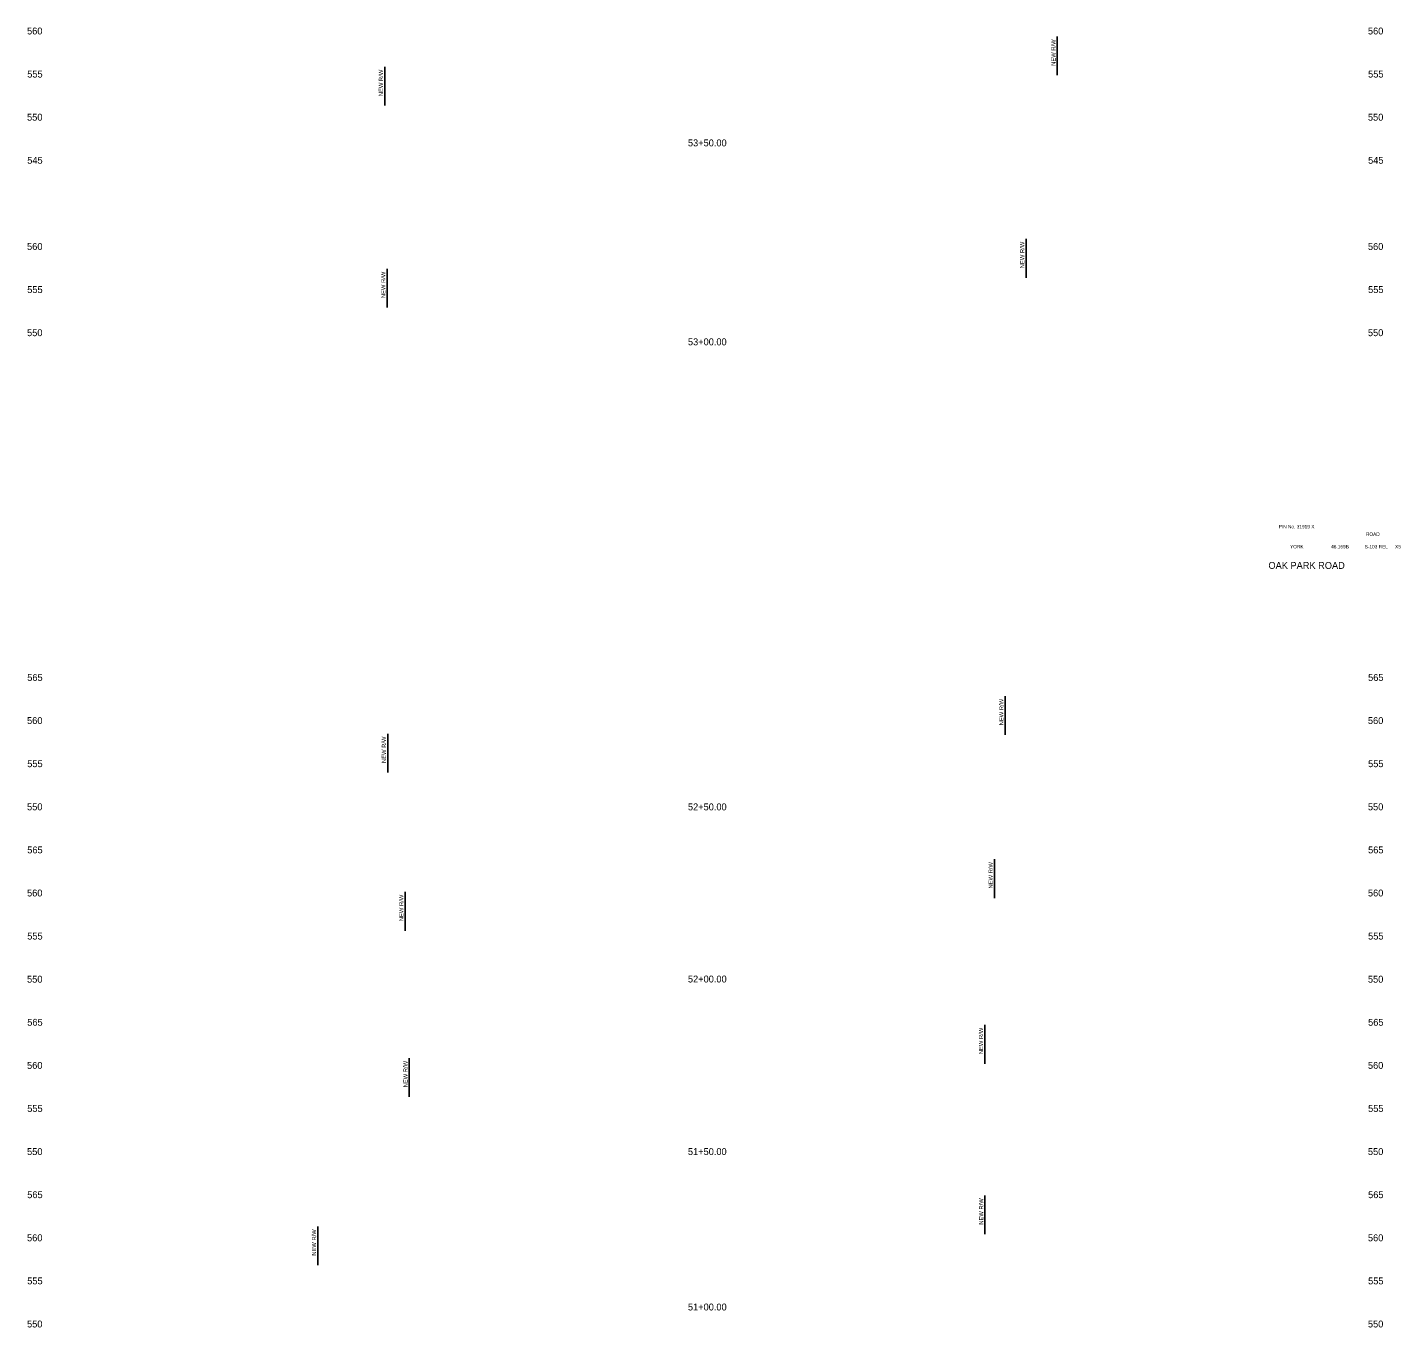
# Model space of a CAD drawing. Extents: x 1001 to 1161, y 1005 to 3518.
# Drawn here: x 1001.2 to 1160.4, y 1470.1 to 1620.9 of the extents above; entities that cross this region are included whole.
import ezdxf

# ---------------------------------------------------------------- set-up
doc = ezdxf.new("R2010")
doc.units = 0
for name, color, linetype in [('RD_SHT_TX', 7, 'Continuous'), ('RD_XS_NewRW', 7, 'Continuous'), ('RD_XS_TX_Elev_EX', 7, 'Continuous'), ('RD_XS_TX_Station', 7, 'Continuous')]:
    doc.layers.add(name, color=color, linetype=linetype)

msp = doc.modelspace()

# ---------------------------------------------------------------- linework, layer by layer
at = {"layer": 'RD_XS_NewRW'}
for p, q in [((1120.61, 1619.86), (1120.61, 1615.36)), ((1042.62, 1616.34), (1042.62, 1611.84)), ((1116.99, 1596.38), (1116.99, 1591.88)), ((1042.9, 1592.91), (1042.9, 1588.41)), ((1114.57, 1543.35), (1114.57, 1538.85)), ((1042.97, 1538.98), (1042.97, 1534.48)), ((1113.33, 1524.42), (1113.33, 1519.92)), ((1044.99, 1520.62), (1044.99, 1516.12)), ((1112.21, 1505.2), (1112.21, 1500.7)), ((1045.47, 1501.35), (1045.47, 1496.85)), ((1112.23, 1485.41), (1112.23, 1480.91)), ((1034.86, 1481.82), (1034.86, 1477.32))]:
    msp.add_line(p, q, dxfattribs=at)

# ---------------------------------------------------------------- texts
at = {"layer": 'RD_SHT_TX'}
for s, height, p in [('PIN No. 31919 X', 0.4, (1146.29, 1562.8)), ('ROAD', 0.4, (1156.41, 1561.93)), ('YORK', 0.4, (1147.61, 1560.48)), ('46.169B', 0.4, (1152.37, 1560.48)), ('S-103 REL', 0.4, (1156.26, 1560.48)), ('X5', 0.4, (1159.79, 1560.48)), ('OAK PARK ROAD', 0.8, (1145.1, 1558.1))]:
    msp.add_text(s, height=height, dxfattribs=at).set_placement(p)
at = {"layer": 'RD_XS_NewRW'}
for p in [(1120.41, 1616.46), (1042.42, 1612.94), (1116.79, 1592.98), (1042.7, 1589.51), (1114.37, 1539.95), (1042.77, 1535.58), (1113.13, 1521.02), (1044.79, 1517.23), (1112.01, 1501.8), (1045.27, 1497.95), (1112.03, 1482.02), (1034.66, 1478.42)]:
    msp.add_text('NEW R/W ', height=0.488, rotation=90, dxfattribs=at).set_placement(p)
at = {"layer": 'RD_XS_TX_Elev_EX'}
for s, p in [('560', (1001.14, 1620.1)), ('560', (1156.64, 1620.1)), ('555', (1001.16, 1615.1)), ('555', (1156.66, 1615.1)), ('550', (1001.14, 1610.1)), ('550', (1156.64, 1610.1)), ('545', (1001.16, 1605.1)), ('545', (1156.66, 1605.1)), ('560', (1001.14, 1595.1)), ('560', (1156.64, 1595.1)), ('555', (1001.16, 1590.1)), ('555', (1156.66, 1590.1)), ('550', (1001.14, 1585.1)), ('550', (1156.64, 1585.1)), ('565', (1001.16, 1545.1)), ('565', (1156.66, 1545.1)), ('560', (1001.14, 1540.1)), ('560', (1156.64, 1540.1)), ('555', (1001.16, 1535.1)), ('555', (1156.66, 1535.1)), ('550', (1001.14, 1530.1)), ('550', (1156.64, 1530.1)), ('565', (1001.16, 1525.1)), ('565', (1156.66, 1525.1)), ('560', (1001.14, 1520.1)), ('560', (1156.64, 1520.1)), ('555', (1001.16, 1515.1)), ('555', (1156.66, 1515.1)), ('550', (1001.14, 1510.1)), ('550', (1156.64, 1510.1)), ('565', (1001.16, 1505.1)), ('565', (1156.66, 1505.1)), ('560', (1001.14, 1500.1)), ('560', (1156.64, 1500.1)), ('555', (1001.16, 1495.1)), ('555', (1156.66, 1495.1)), ('550', (1001.14, 1490.1)), ('550', (1156.64, 1490.1)), ('565', (1001.16, 1485.1)), ('565', (1156.66, 1485.1)), ('560', (1001.14, 1480.1)), ('560', (1156.64, 1480.1)), ('555', (1001.16, 1475.1)), ('555', (1156.66, 1475.1)), ('550', (1001.14, 1470.1)), ('550', (1156.64, 1470.1))]:
    msp.add_text(s, height=0.8, dxfattribs=at).set_placement(p)
at = {"layer": 'RD_XS_TX_Station'}
for s, p in [('53+50.00', (1077.78, 1607.12)), ('53+00.00', (1077.78, 1584.04)), ('52+50.00', (1077.78, 1530.09)), ('52+00.00', (1077.78, 1510.12)), ('51+50.00', (1077.78, 1490.1)), ('51+00.00', (1077.78, 1472.07))]:
    msp.add_text(s, height=0.8, dxfattribs=at).set_placement(p)

doc.saveas('drawing.dxf')
